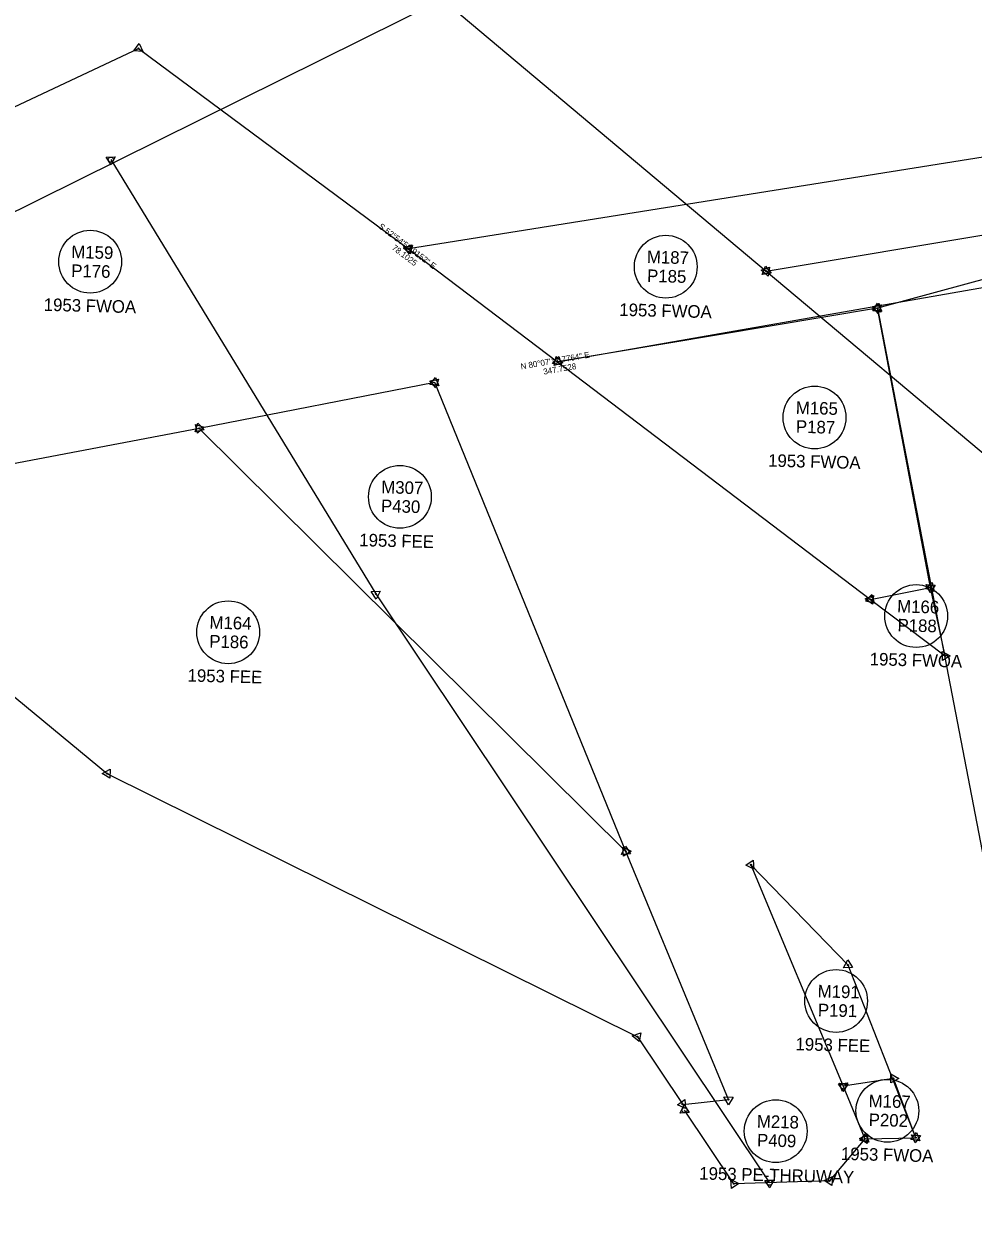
# Model space of a CAD drawing. Extents: x 325018 to 414989, y 1517547 to 1550415.
# Drawn here: x 363499 to 363895, y 1523766 to 1524267 of the extents above; entities that cross this region are included whole.
import ezdxf

# ---------------------------------------------------------------- set-up
doc = ezdxf.new("R2010")
doc.units = 0
for name, color, linetype in [('ADEFAULT', 7, 'Continuous'), ('Level 56', 7, 'Continuous'), ('MEE', 7, 'Continuous'), ('MHB', 7, 'Continuous'), ('MHBWOA', 7, 'Continuous'), ('MRBL1', 7, 'Continuous'), ('MRBL2', 7, 'Continuous'), ('XDEFAULT_P', 7, 'Continuous'), ('XDEFAULT_P_T', 7, 'Continuous')]:
    doc.layers.add(name, color=color, linetype=linetype)

msp = doc.modelspace()

# ---------------------------------------------------------------- linework, layer by layer
at = {"layer": 'ADEFAULT'}
for points in [[(363657.36, 1524173.12), (363660.84, 1524174.6)], [(363660.37, 1524170.85), (363657.36, 1524173.12)], [(363657.49, 1524173.64), (363661.22, 1524174.24)], [(363659.87, 1524170.71), (363657.49, 1524173.64)], [(363661.22, 1524174.24), (363659.87, 1524170.71)], [(363660.84, 1524174.6), (363660.37, 1524170.85)], [(363719.74, 1524125.14), (363722.35, 1524127.88)], [(363723.41, 1524124.26), (363719.74, 1524125.14)], [(363722.35, 1524127.88), (363723.41, 1524124.26)], [(363571.35, 1524095.84), (363570.5, 1524099.52)], [(363570.5, 1524099.52), (363574.11, 1524098.42)], [(363574.11, 1524098.42), (363571.35, 1524095.84)], [(363531.46, 1523953.79), (363534.83, 1523955.51)], [(363534.63, 1523951.74), (363531.46, 1523953.79)], [(363534.83, 1523955.51), (363534.63, 1523951.74)], [(363748.5, 1523919.99), (363750.17, 1523923.39)], [(363750.17, 1523923.39), (363752.27, 1523920.25)], [(363752.27, 1523920.25), (363748.5, 1523919.99)], [(363753.03, 1523844.26), (363756.6, 1523845.47)], [(363755.86, 1523841.77), (363753.03, 1523844.26)], [(363756.6, 1523845.47), (363755.86, 1523841.77)], [(363793.18, 1523815.37), (363791.34, 1523818.67)], [(363791.34, 1523818.67), (363795.12, 1523818.62)], [(363795.12, 1523818.62), (363793.18, 1523815.37)], [(363771.9, 1523815.39), (363775, 1523817.55)], [(363775.32, 1523813.79), (363771.9, 1523815.39)], [(363775, 1523817.55), (363775.32, 1523813.79)]]:
    msp.add_lwpolyline(points, dxfattribs=at)
for centre, radius in [((363659.53, 1524172.86), 1.09), ((363659.52, 1524172.86), 1.09), ((363721.83, 1524125.76), 0.227), ((363571.99, 1524097.92), 0.227), ((363533.64, 1523953.68), 0.227), ((363750.31, 1523921.21), 0.227), ((363755.17, 1523843.83), 0.227), ((363774.08, 1523815.58), 0.227), ((363793.21, 1523817.56), 0.227)]:
    msp.add_circle(centre, radius, dxfattribs=at)
at = {"layer": 'Level 56'}
for centre in [(363526.45, 1524167.53), (363767, 1524165.43), (363829.19, 1524102.44), (363655.91, 1524069.3), (363871.65, 1524019.51), (363584.15, 1524012.75), (363838.19, 1523858.75), (363859.62, 1523812.9), (363812.96, 1523804.39)]:
    msp.add_circle(centre, 13.12, dxfattribs=at)
at = {"layer": 'MEE'}
for p, q in [((363795.43, 1523782.4), (363774.85, 1523813.15)), ((363850.2, 1523801.22), (363835.41, 1523783.61)), ((363835.41, 1523783.61), (363795.43, 1523782.4))]:
    msp.add_line(p, q, dxfattribs=at)
for points in [[(363773.04, 1523811.94), (363774.7, 1523815.33)], [(363774.7, 1523815.33), (363776.81, 1523812.19)], [(363776.81, 1523812.19), (363773.04, 1523811.94)], [(363848.15, 1523800.48), (363850.58, 1523803.37)], [(363850.58, 1523803.37), (363851.87, 1523799.82)], [(363851.87, 1523799.82), (363848.15, 1523800.48)], [(363794.43, 1523780.46), (363794.25, 1523784.24)], [(363794.25, 1523784.24), (363797.61, 1523782.51)], [(363833.23, 1523783.77), (363836.63, 1523785.42)], [(363836.36, 1523781.65), (363833.23, 1523783.77)], [(363836.63, 1523785.42), (363836.36, 1523781.65)], [(363797.61, 1523782.51), (363794.43, 1523780.46)]]:
    msp.add_lwpolyline(points, dxfattribs=at)
for centre, radius in [((363774.85, 1523813.15), 1.09), ((363850.2, 1523801.22), 1.09), ((363835.41, 1523783.61), 0.227), ((363795.43, 1523782.4), 0.227)]:
    msp.add_circle(centre, radius, dxfattribs=at)
at = {"layer": 'MHB'}
for p, q in [((363169.95, 1524079.88), (363546.67, 1524256.55)), ((363546.67, 1524256.55), (363659.53, 1524172.86)), ((363670.46, 1524117.02), (363571.99, 1524097.92)), ((363750.31, 1523921.21), (363670.46, 1524117.02)), ((363571.99, 1524097.92), (363398.85, 1524064.87)), ((363571.99, 1524097.92), (363750.31, 1523921.21)), ((363750.31, 1523921.21), (363571.99, 1524097.92)), ((363398.85, 1524064.87), (363533.64, 1523953.68)), ((363533.64, 1523953.68), (363755.17, 1523843.83)), ((363793.21, 1523817.56), (363750.31, 1523921.21)), ((363843.17, 1523873.72), (363802.61, 1523915.61)), ((363802.61, 1523915.61), (363841.19, 1523823.15)), ((363871.45, 1523801.65), (363843.17, 1523873.72)), ((363755.17, 1523843.83), (363774.08, 1523815.58)), ((363774.08, 1523815.58), (363793.21, 1523817.56))]:
    msp.add_line(p, q, dxfattribs=at)
for points in [[(363544.69, 1524255.65), (363546.89, 1524258.72)], [(363546.89, 1524258.72), (363548.45, 1524255.27)], [(363548.45, 1524255.27), (363544.69, 1524255.65)], [(363657.36, 1524173.1), (363660.82, 1524174.61)], [(363660.82, 1524174.61), (363660.39, 1524170.85)], [(363660.39, 1524170.85), (363657.36, 1524173.1)], [(363668.39, 1524117.74), (363672.1, 1524118.46)], [(363668.44, 1524116.2), (363670.76, 1524119.19)], [(363670.76, 1524119.19), (363672.18, 1524115.69)], [(363672.1, 1524118.46), (363670.87, 1524114.89)], [(363670.87, 1524114.89), (363668.39, 1524117.74)], [(363672.18, 1524115.69), (363668.44, 1524116.2)], [(363570.39, 1524096.43), (363571.49, 1524100.05)], [(363571.49, 1524100.05), (363574.07, 1524097.29)], [(363574.07, 1524097.29), (363570.39, 1524096.43)], [(363749.35, 1523919.25), (363749.1, 1523923.02)], [(363749.1, 1523923.02), (363752.49, 1523921.35)], [(363752.49, 1523921.35), (363749.35, 1523919.25)], [(363800.43, 1523915.48), (363803.59, 1523917.56)], [(363803.81, 1523913.79), (363800.43, 1523915.48)], [(363803.59, 1523917.56), (363803.81, 1523913.79)], [(363841.34, 1523872.54), (363843.07, 1523875.9)], [(363843.07, 1523875.9), (363845.11, 1523872.72)], [(363845.11, 1523872.72), (363841.34, 1523872.54)], [(363839.45, 1523824.47), (363843.2, 1523823.99)], [(363840.91, 1523820.99), (363839.45, 1523824.47)], [(363843.2, 1523823.99), (363840.91, 1523820.99)], [(363869.43, 1523800.86), (363871.78, 1523803.81)], [(363871.78, 1523803.81), (363873.16, 1523800.3)], [(363873.16, 1523800.3), (363869.43, 1523800.86)]]:
    msp.add_lwpolyline(points, dxfattribs=at)
for centre, radius in [((363546.67, 1524256.55), 0.227), ((363659.53, 1524172.86), 1.09), ((363670.45, 1524117.02), 1.09), ((363670.46, 1524117.03), 1.09), ((363571.99, 1524097.92), 0.227), ((363750.31, 1523921.21), 0.227), ((363802.61, 1523915.61), 0.227), ((363843.17, 1523873.72), 0.227), ((363841.19, 1523823.15), 1.09), ((363871.45, 1523801.66), 1.09)]:
    msp.add_circle(centre, radius, dxfattribs=at)
at = {"layer": 'MHBWOA'}
for p, q in [((364010.94, 1524229.04), (363659.53, 1524172.86)), ((363721.83, 1524125.76), (364064.43, 1524185.43)), ((363659.53, 1524172.86), (363721.83, 1524125.76)), ((363903.69, 1524161.16), (363855.46, 1524148.06)), ((363855.46, 1524148.06), (363721.83, 1524125.76)), ((363877.69, 1524031.46), (363855.46, 1524148.06)), ((363855.46, 1524148.06), (363921.53, 1523805.31)), ((363721.83, 1524125.76), (363852.57, 1524026.43)), ((363852.57, 1524026.43), (363877.69, 1524031.46)), ((363883.73, 1524002.88), (363877.69, 1524031.46)), ((363852.57, 1524026.43), (363883.73, 1524002.88)), ((363862.2, 1523826.4), (363841.19, 1523823.15)), ((363841.19, 1523823.15), (363850.2, 1523801.22)), ((363871.45, 1523801.65), (363862.2, 1523826.4)), ((363850.2, 1523801.22), (363871.45, 1523801.65))]:
    msp.add_line(p, q, dxfattribs=at)
for points in [[(363853.32, 1524147.65), (363856.18, 1524150.12)], [(363853.42, 1524148.82), (363857.14, 1524149.45)], [(363855.82, 1524145.91), (363853.42, 1524148.82)], [(363853.53, 1524147.03), (363855.53, 1524150.24)], [(363855.53, 1524150.24), (363857.31, 1524146.9)], [(363857.14, 1524149.45), (363855.82, 1524145.91)], [(363856.18, 1524150.12), (363856.89, 1524146.41)], [(363856.89, 1524146.41), (363853.32, 1524147.65)], [(363857.31, 1524146.9), (363853.53, 1524147.03)], [(363720.32, 1524124.19), (363721.22, 1524127.86)], [(363723.95, 1524125.24), (363720.32, 1524124.19)], [(363721.22, 1524127.86), (363723.95, 1524125.24)], [(363875.56, 1524031.01), (363878.37, 1524033.53)], [(363878.37, 1524033.53), (363879.15, 1524029.84)], [(363850.41, 1524026.7), (363853.89, 1524028.17)], [(363850.49, 1524025.79), (363853.06, 1524028.55)], [(363853.06, 1524028.55), (363854.17, 1524024.94)], [(363853.89, 1524028.17), (363853.42, 1524024.42)], [(363879.15, 1524029.84), (363875.56, 1524031.01)], [(363877.54, 1524029.28), (363875.88, 1524032.68)], [(363875.88, 1524032.68), (363879.65, 1524032.42)], [(363879.65, 1524032.42), (363877.54, 1524029.28)], [(363853.42, 1524024.42), (363850.41, 1524026.7)], [(363854.17, 1524024.94), (363850.49, 1524025.79)], [(363882.72, 1524000.95), (363882.56, 1524004.72)], [(363882.56, 1524004.72), (363885.91, 1524002.97)], [(363885.91, 1524002.97), (363882.72, 1524000.95)], [(363861.1, 1523824.52), (363861.12, 1523828.3)], [(363861.12, 1523828.3), (363864.38, 1523826.39)], [(363839.16, 1523823.94), (363842.89, 1523824.52)], [(363841.52, 1523821), (363839.16, 1523823.94)], [(363839.46, 1523824.48), (363843.2, 1523823.98)], [(363840.9, 1523820.99), (363839.46, 1523824.48)], [(363843.2, 1523823.98), (363840.9, 1523820.99)], [(363842.89, 1523824.52), (363841.52, 1523821)], [(363864.38, 1523826.39), (363861.1, 1523824.52)], [(363848.02, 1523801.34), (363851.39, 1523803.04)], [(363851.39, 1523803.04), (363851.18, 1523799.27)], [(363871.3, 1523799.48), (363869.65, 1523802.88)], [(363869.65, 1523802.88), (363873.42, 1523802.6)], [(363851.18, 1523799.27), (363848.02, 1523801.34)], [(363873.42, 1523802.6), (363871.3, 1523799.48)]]:
    msp.add_lwpolyline(points, dxfattribs=at)
for centre, radius in [((363855.46, 1524148.06), 1.09), ((363855.46, 1524148.06), 1.09), ((363855.46, 1524148.06), 0.227), ((363721.83, 1524125.76), 0.227), ((363877.69, 1524031.46), 1.09), ((363877.69, 1524031.46), 0.227), ((363852.58, 1524026.43), 1.09), ((363852.57, 1524026.43), 0.227), ((363883.73, 1524002.88), 0.227), ((363841.19, 1523823.15), 1.09), ((363841.19, 1523823.15), 1.09), ((363862.2, 1523826.4), 0.227), ((363850.2, 1523801.22), 0.227), ((363871.45, 1523801.65), 0.227)]:
    msp.add_circle(centre, radius, dxfattribs=at)
at = {"layer": 'MRBL1'}
for p, q in [((362781.13, 1523834.71), (363673.76, 1524277.12)), ((363809.01, 1524163.56), (364210.4, 1524230.78)), ((363535.11, 1524210.15), (363645.83, 1524028.77)), ((363645.83, 1524028.77), (363810.42, 1523782.85))]:
    msp.add_line(p, q, dxfattribs=at)
for points in [[(363533.2, 1524211.19), (363536.97, 1524211.28)], [(363535.17, 1524207.96), (363533.2, 1524211.19)], [(363536.97, 1524211.28), (363535.17, 1524207.96)], [(363807.33, 1524162.17), (363808.65, 1524165.7)], [(363808.65, 1524165.7), (363811.05, 1524162.79)], [(363811.05, 1524162.79), (363807.33, 1524162.17)], [(363643.9, 1524029.77), (363647.67, 1524029.94)], [(363645.93, 1524026.59), (363643.9, 1524029.77)], [(363647.67, 1524029.94), (363645.93, 1524026.59)], [(363808.46, 1523783.82), (363812.23, 1523784.06)], [(363810.56, 1523780.68), (363808.46, 1523783.82)], [(363812.23, 1523784.06), (363810.56, 1523780.68)]]:
    msp.add_lwpolyline(points, dxfattribs=at)
for centre, radius in [((363535.12, 1524210.14), 1.09), ((363809.01, 1524163.56), 1.09), ((363645.83, 1524028.77), 0.227), ((363810.42, 1523782.85), 1.09)]:
    msp.add_circle(centre, radius, dxfattribs=at)
at = {"layer": 'MRBL2'}
for p, q in [((363673.76, 1524277.12), (363809.01, 1524163.56)), ((363809.01, 1524163.56), (364281.98, 1523766.42))]:
    msp.add_line(p, q, dxfattribs=at)
for points in [[(363806.86, 1524163.93), (363810.41, 1524165.22)], [(363809.75, 1524161.5), (363806.86, 1524163.93)], [(363810.41, 1524165.22), (363809.75, 1524161.5)]]:
    msp.add_lwpolyline(points, dxfattribs=at)
msp.add_circle((363809.01, 1524163.56), 0.227, dxfattribs=at)
at = {"layer": 'XDEFAULT_P'}
for p, q in [((363721.83, 1524125.76), (364064.43, 1524185.43)), ((363659.53, 1524172.86), (363721.83, 1524125.76))]:
    msp.add_line(p, q, dxfattribs=at)

# ---------------------------------------------------------------- texts
at = {"layer": 'Level 56'}
for s, height, p in [('M159', 5.249, (363518.52, 1524169.05)), ('M187', 5.249, (363759.07, 1524166.95)), ('P176', 5.249, (363518.49, 1524161.17)), ('P185', 5.249, (363759.16, 1524159.07)), ('1953 FWOA', 5.249, (363507, 1524147.01)), ('1953 FWOA', 5.249, (363747.55, 1524144.92)), ('M165', 5.249, (363821.31, 1524103.96)), ('P187', 5.249, (363821.35, 1524096.08)), ('1953 FWOA', 5.249, (363809.74, 1524081.93)), ('M307', 5.249, (363648.06, 1524070.82)), ('P430', 5.249, (363647.96, 1524062.94)), ('1953 FEE', 5.249, (363638.88, 1524048.72)), ('M166', 5.249, (363863.65, 1524021.03)), ('M164', 5.249, (363576.27, 1524014.26)), ('P188', 5.249, (363863.81, 1524013.14)), ('P186', 5.249, (363576.19, 1524006.39)), ('1953 FWOA', 5.249, (363852.2, 1523998.99)), ('1953 FEE', 5.249, (363567.12, 1523992.17)), ('M191', 5.249, (363830.44, 1523860.27)), ('P191', 5.249, (363830.53, 1523852.39)), ('1953 FEE', 5.249, (363821.17, 1523838.17)), ('M167', 5.249, (363851.74, 1523814.42)), ('M218', 5.249, (363805.03, 1523805.91)), ('P202', 5.249, (363851.78, 1523806.54)), ('P409', 5.249, (363805.1, 1523798.03)), ('1953 FWOA', 5.249, (363840.17, 1523792.39)), ('1953 PE-THRUWAY', 5.2493, (363780.96, 1523784.2))]:
    msp.add_text(s, height=height, rotation=358.5141, dxfattribs=at).set_placement(p)
at = {"layer": 'XDEFAULT_P_T'}
for s, height, rotation, p in [('S 52%%d54\'59.9152" E', 2.5008, 322.9166, (363646.72, 1524181.76)), ('78.1025', 2.501, 322.9166, (363652.31, 1524172.83)), ('N 80%%d07\'11.7764" E', 2.5008, 9.8801, (363706.58, 1524122.47)), ('347.7528', 2.501, 9.8801, (363716.05, 1524120.31))]:
    msp.add_text(s, height=height, rotation=rotation, dxfattribs=at).set_placement(p)

doc.saveas('drawing.dxf')
